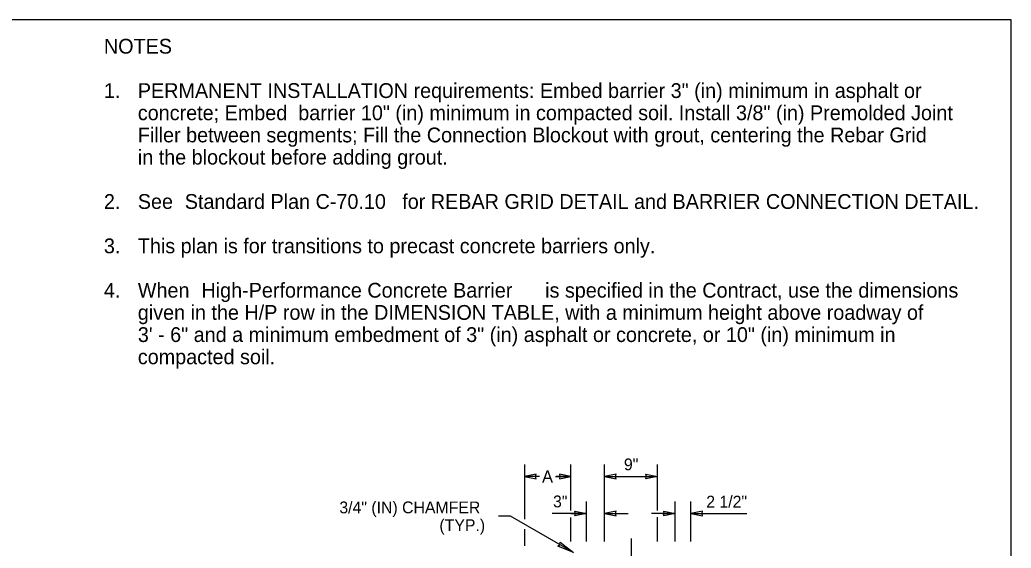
# Model space of a CAD drawing. Extents: x 99862 to 103151, y 100000 to 102076.
# Drawn here: x 101810 to 103151, y 101361 to 102076 of the extents above; entities that cross this region are included whole.
import ezdxf

# ---------------------------------------------------------------- set-up
doc = ezdxf.new("R2010")
doc.units = 0
for name, color, linetype in [('Level 1', 7, 'Continuous'), ('Level 15', 7, 'Continuous'), ('Level 20', 7, 'Continuous'), ('Level 60', 7, 'Continuous')]:
    doc.layers.add(name, color=color, linetype=linetype)

msp = doc.modelspace()

# ---------------------------------------------------------------- linework, layer by layer
at = {"layer": 'Level 1'}
msp.add_lwpolyline([(99862, 99999.5), (103151, 99999.5), (103151, 102075.5), (99862, 102075.5)], close=True, dxfattribs=at)
at = {"layer": 'Level 15'}
for p, q in [((102492.7, 101474), (102492.7, 101400.3)), ((102555.5, 101412.1), (102555.5, 101474)), ((102600.7, 101370), (102600.7, 101474)), ((102672.6, 101412), (102672.6, 101474)), ((102512.7, 101458), (102492.7, 101458)), ((102534.4, 101458), (102555.5, 101458)), ((102555.5, 101458), (102535.5, 101458)), ((102600.7, 101458), (102672.6, 101458)), ((102576.7, 101370), (102576.7, 101424)), ((102696.6, 101370), (102696.6, 101424)), ((102717.8, 101370), (102717.8, 101423.9)), ((102473.6, 101404.4), (102457.6, 101404.4)), ((102559.1, 101355.1), (102473.6, 101404.4)), ((102576.7, 101408), (102530.2, 101408)), ((102555.5, 101408), (102576.7, 101408)), ((102600.7, 101408), (102632.7, 101408)), ((102600.7, 101408), (102616.1, 101408)), ((102696.6, 101408), (102664.6, 101408)), ((102679, 101408), (102696.6, 101408)), ((102717.8, 101407.9), (102738.9, 101407.9)), ((102717.8, 101407.9), (102793.6, 101407.9)), ((102555.5, 101370), (102555.5, 101402.5)), ((102672.6, 101370), (102672.6, 101403)), ((102492.7, 101386.5), (102492.7, 101364)), ((102636.7, 101374), (102636.7, 100922.8))]:
    msp.add_line(p, q, dxfattribs=at)
for points in [[(102492.7, 101458), (102508.4, 101454.9), (102507.7, 101458), (102508.4, 101461.1)], [(102555.5, 101458), (102539.8, 101461.1), (102540.6, 101458), (102539.8, 101454.9)], [(102600.7, 101458), (102616.4, 101454.9), (102615.7, 101458), (102616.4, 101461.1)], [(102672.6, 101458), (102656.9, 101454.9), (102657.6, 101458), (102656.9, 101461.1)], [(102576.7, 101408), (102560.9, 101404.9), (102561.7, 101408), (102560.9, 101411.1)], [(102600.7, 101408), (102616.4, 101404.9), (102615.7, 101408), (102616.4, 101411.1)], [(102696.6, 101408), (102680.9, 101404.9), (102681.6, 101408), (102680.9, 101411.1)], [(102717.8, 101407.9), (102733.5, 101404.8), (102732.8, 101407.9), (102733.5, 101411)], [(102559.1, 101355.1), (102537.8, 101363.9), (102540.3, 101365.9), (102540.8, 101369.1)]]:
    msp.add_lwpolyline(points, close=True, dxfattribs=at)
at = {"layer": 'Level 60'}
msp.add_line((103151, 102075.5), (103151, 102075.5), dxfattribs=at)

# ---------------------------------------------------------------- texts
at = {"layer": 'Level 15'}
msp.add_text('A', height=16.5, dxfattribs=at).set_placement((102516.4, 101449.7))
at = {"layer": 'Level 20'}
for s, height, p in [('NOTES', 20, (101923.6, 102029.8)), ('1.', 20, (101923.6, 101969.8)), ('PERMANENT INSTALLATION requirements: Embed barrier 3" (in) minimum in asphalt or ', 20, (101969.5, 101969.8)), ('concrete; Embed  barrier 10" (in) minimum in compacted soil. Install 3/8" (in) Premolded Joint', 20, (101969.5, 101939.8)), ('Filler between segments; Fill the Connection Blockout with grout, centering the Rebar Grid ', 20, (101969.5, 101909.8)), ('in the blockout before adding grout.', 20, (101969.5, 101879.8)), ('2.', 20, (101923.6, 101819.8)), ('See ', 20, (101969.5, 101819.8)), ('Standard Plan C-70.10', 20, (102033, 101819.8)), (' for REBAR GRID DETAIL and BARRIER CONNECTION DETAIL.', 20, (102319.8, 101819.8)), ('3.', 20, (101923.6, 101759.8)), ('This plan is for transitions to precast concrete barriers only.', 20, (101969.5, 101759.8)), ('4.', 20, (101923.6, 101699.8)), ('When ', 20, (101969.5, 101699.8)), ('High-Performance Concrete Barrier', 20, (102055.6, 101699.8)), (' is specified in the Contract, use the dimensions', 20, (102513.1, 101699.8)), ('given in the H/P row in the DIMENSION TABLE, with a minimum height above roadway of ', 20, (101969.5, 101669.8)), ('3\' - 6" and a minimum embedment of 3" (in) asphalt or concrete, or 10" (in) minimum in ', 20, (101969.5, 101639.8)), ('compacted soil.', 20, (101969.5, 101609.8)), ('9"', 16, (102627.1, 101466.3)), ('3"', 16, (102531.2, 101416.2)), ('2 1/2"', 16, (102738.5, 101415.9))]:
    msp.add_text(s, height=height, dxfattribs=at).set_placement(p)
for s, p in [(' 3/4" (IN) CHAMFER', (102236.2, 101408.1)), ('(TYP.)', (102377.5, 101384.1))]:
    msp.add_text(s, height=16, rotation=360, dxfattribs=at).set_placement(p)

doc.saveas('drawing.dxf')
